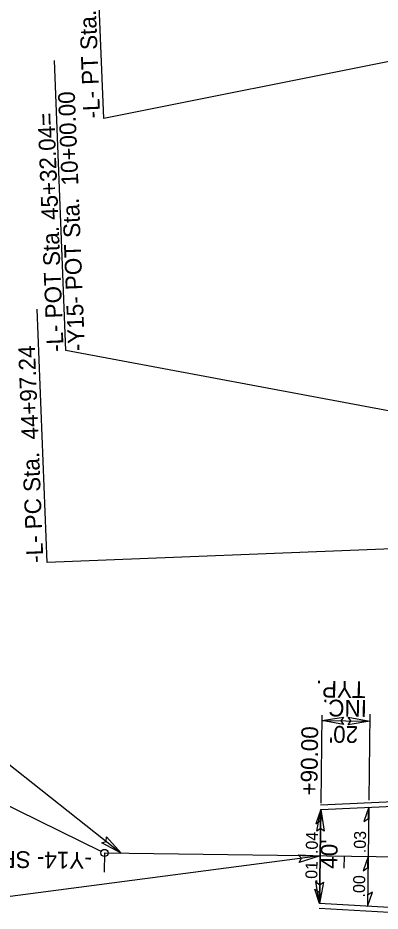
# Model space of a CAD drawing. Extents: x 1627861 to 1629601, y 761281 to 766239.
# Drawn here: x 1628115.8 to 1628267, y 764815.3 to 765188 of the extents above; entities that cross this region are included whole.
import ezdxf

# ---------------------------------------------------------------- set-up
doc = ezdxf.new("R2010")
doc.units = 0
for name, color, linetype in [('Exist Other Culture Sign Leader', 7, 'Continuous'), ('Exist Property Tie Line Text', 7, 'Continuous'), ('Exist Right of Way Line Leader', 7, 'Continuous'), ('Exist Right of Way Monument Text', 7, 'Continuous'), ('Exist Utilities Gas Meter CELL', 7, 'Continuous'), ('Exist Utilities Gas Meter Cogo Elevation', 7, 'Continuous'), ('Exist Utilities Gas Meter Cogo Number', 7, 'Continuous'), ('Exist Utilities Power UG Cable SUE LOS B Cogo Point CELL', 7, 'Continuous'), ('Exist Utilities Water Meter Cogo Elevation', 7, 'Continuous'), ('Exist Utilities Water UG Line SUE LOS B Cogo Number', 7, 'Continuous'), ('Scratch_Level_0', 7, 'Continuous'), ('Typical Terminator CELL', 7, 'Continuous')]:
    doc.layers.add(name, color=color, linetype=linetype)

msp = doc.modelspace()

# ---------------------------------------------------------------- linework, layer by layer
at = {"layer": 'Exist Property Tie Line Text'}
msp.add_line((1628251.95, 764838.26), (1628251.89, 764833.26), dxfattribs=at)
at = {"layer": 'Exist Right of Way Line Leader'}
for p, q in [((1628151.63, 765145.98), (1628147.35, 765254.61)), ((1628346.1, 765184.88), (1628151.63, 765145.98)), ((1628135.9, 765049.17), (1628131.12, 765170.25)), ((1628128.07, 764960.79), (1628123.9, 765066.47)), ((1628369.83, 765005.5), (1628135.9, 765049.17)), ((1628373.12, 764970.45), (1628128.07, 764960.79)), ((1628087.22, 764896.19), (1628158.92, 764839.46)), ((1628150.61, 764840.21), (1628077.26, 764876.02))]:
    msp.add_line(p, q, dxfattribs=at)
msp.add_circle((1628151.96, 764839.55), 1.5, dxfattribs=at)
at = {"layer": 'Exist Right of Way Monument Text'}
for p, q in [((1628242.2, 764857.68), (1628288.04, 764859.79)), ((1628286.66, 764815.8), (1628241.69, 764818.41))]:
    msp.add_line(p, q, dxfattribs=at)
at = {"layer": 'Exist Utilities Gas Meter CELL'}
msp.add_line((1628151.96, 764839.55), (1628378.39, 764836.61), dxfattribs=at)
msp.add_line((1628151.96, 764839.55), (1628378.39, 764836.61), dxfattribs=at)
at = {"layer": 'Exist Utilities Gas Meter Cogo Elevation'}
for p, q in [((1628242.11, 764859.68), (1628287.95, 764861.79)), ((1628286.55, 764813.81), (1628241.58, 764816.42))]:
    msp.add_line(p, q, dxfattribs=at)
at = {"layer": 'Exist Utilities Gas Meter Cogo Number'}
for points in [[(1628251.66, 764893.12), (1628242.68, 764894.78), (1628251.75, 764896.27), (1628250.58, 764894.68)], [(1628253.7, 764896.19), (1628262.68, 764894.52), (1628253.61, 764893.04), (1628254.78, 764894.63)], [(1628240.54, 764848.7), (1628242.2, 764857.68), (1628243.69, 764848.61), (1628242.1, 764849.78)], [(1628152.83, 764846.26), (1628158.92, 764839.46), (1628150.83, 764843.82), (1628152.73, 764844.37)], [(1628232.83, 764838.75), (1628241.95, 764838.39), (1628233.19, 764835.62), (1628234.12, 764837.36)], [(1628243.36, 764827.39), (1628241.69, 764818.41), (1628240.21, 764827.48), (1628241.8, 764826.31)]]:
    msp.add_lwpolyline(points, close=True, dxfattribs=at)
at = {"layer": 'Exist Utilities Water Meter Cogo Elevation'}
msp.add_line((1628151.96, 764839.55), (1628151.86, 764831.56), dxfattribs=at)
at = {"layer": 'Exist Utilities Water UG Line SUE LOS B Cogo Number'}
for p, q in [((1628242.2, 764857.68), (1628241.69, 764818.41)), ((1628262.22, 764858.6), (1628261.68, 764817.25))]:
    msp.add_line(p, q, dxfattribs=at)
at = {"layer": 'Scratch_Level_0'}
for p, q in [((1628242.71, 764897.1), (1628242.24, 764860.38)), ((1628242.68, 764894.78), (1628262.68, 764894.52)), ((1628262.72, 764897.52), (1628262.26, 764861.64)), ((1628241.69, 764818.41), (1628242.2, 764857.68)), ((1628241.95, 764838.39), (1628083.84, 764817.64))]:
    msp.add_line(p, q, dxfattribs=at)
at = {"layer": 'Typical Terminator CELL'}
for points in [[(1628242.2, 764857.68), (1628240.13, 764851.7), (1628242.14, 764853.05)], [(1628262.22, 764858.6), (1628260.14, 764852.63), (1628262.16, 764853.98)], [(1628261.95, 764838.13), (1628259.87, 764832.15), (1628261.89, 764833.5)], [(1628241.69, 764818.41), (1628239.77, 764824.44), (1628241.75, 764823.04)], [(1628261.68, 764817.25), (1628263.76, 764823.23), (1628261.74, 764821.88)]]:
    msp.add_lwpolyline(points, close=True, dxfattribs=at)

# ---------------------------------------------------------------- texts
at = {"layer": 'Exist Other Culture Sign Leader'}
msp.add_text('-Y14- SR 1408 (BIESECKER ROAD)', height=7, rotation=179.2561, dxfattribs=at).set_placement((1628146.73, 764839.9))
at = {"layer": 'Exist Right of Way Line Leader'}
for s, p in [('-L- PT Sta.  47+13.70', (1628150.18, 765146.2)), ('-Y15- POT Sta.  10+00.00', (1628143.82, 765049.07)), ('-L- POT Sta. 45+32.04=', (1628134.95, 765048.72)), ('-L- PC Sta.  44+97.24', (1628126.5, 764960.72))]:
    msp.add_text(s, height=7, rotation=92.2582, dxfattribs=at).set_placement(p)
at = {"layer": 'Exist Utilities Power UG Cable SUE LOS B Cogo Point CELL'}
for s, rotation, p in [('TYP.', 179.2561, (1628261, 764911.18)), ('INC.', 179.2561, (1628261.53, 764903.33)), ('+90.00', 89.2561, (1628240.77, 764863.48)), ("20'", 179.2561, (1628257.86, 764892.44)), ("40'", 89.2561, (1628249.14, 764832.92))]:
    msp.add_text(s, height=7, rotation=rotation, dxfattribs=at).set_placement(p)
at = {"layer": 'Exist Utilities Water UG Line SUE LOS B Cogo Number'}
for s, p in [('.04', (1628240.94, 764839.06)), ('.03', (1628260.99, 764839.42)), ('.01', (1628240.74, 764826.87)), ('.00', (1628260.63, 764820.94))]:
    msp.add_text(s, height=5, rotation=89.1874, dxfattribs=at).set_placement(p)

doc.saveas('drawing.dxf')
